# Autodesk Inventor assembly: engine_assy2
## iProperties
Created: 2002-08
Part Number: engine_assy2
Document SubType Name: Assembly
Designer: t_munrn
Control State: 0
Master: False
Checked Out: False
Shininess: 64.0
Length Units: 11269
Angle Units: 11279
Time Units: 11290
Mass Units: 11283
Length Display Precision: 3
Angle Display Precision: 2
Density: 0.0
Volumn: 0.0
Area: 0.0
PropertySet Name: Model Information
Author: t_munrn
